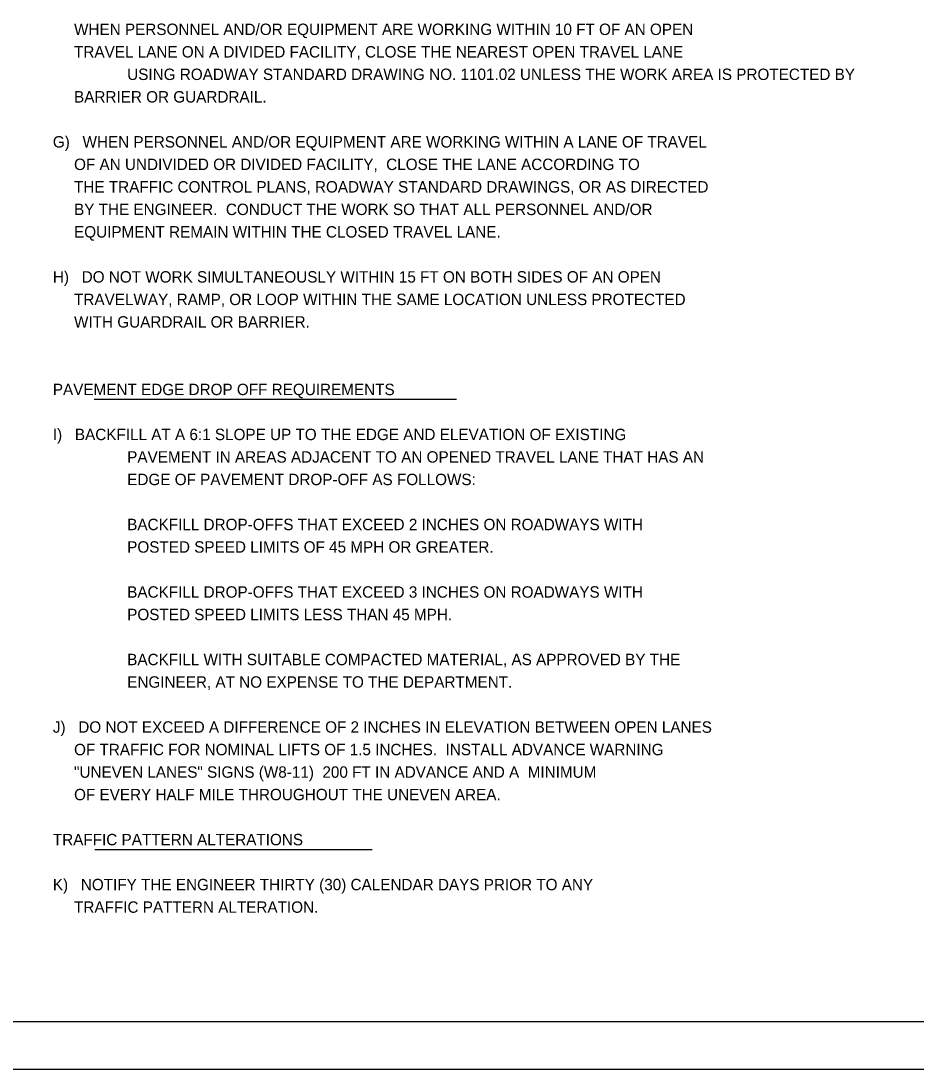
# Model space of a CAD drawing. Extents: x 762655 to 770567, y 650864 to 655190.
# Drawn here: x 763282 to 763752, y 652779 to 653330 of the extents above; entities that cross this region are included whole.
import ezdxf

# ---------------------------------------------------------------- set-up
doc = ezdxf.new("R2010")
doc.units = 0
for name, color, linetype in [('Default', 7, 'Continuous'), ('DEV TRANSPORTATION OPERATIONS PLAN SHEET', 7, 'Continuous'), ('Sheet Plot Border Outside CELL', 7, 'Continuous')]:
    doc.layers.add(name, color=color, linetype=linetype)

msp = doc.modelspace()

# ---------------------------------------------------------------- linework, layer by layer
at = {"layer": 'Default'}
for p, q in [((763320.1, 653130.89), (763510.57, 653130.89)), ((763320.41, 652894.11), (763466.13, 652894.11))]:
    msp.add_line(p, q, dxfattribs=at)
at = {"layer": 'DEV TRANSPORTATION OPERATIONS PLAN SHEET'}
msp.add_lwpolyline([(764317.85, 653853.76), (762817.85, 653853.76), (762817.85, 652803.75), (764317.85, 652803.75)], close=True, dxfattribs=at)
at = {"layer": 'Sheet Plot Border Outside CELL'}
msp.add_lwpolyline([(762654.85, 652778.75), (764342.85, 652778.75), (764342.85, 653878.75), (762654.85, 653878.75)], close=True, dxfattribs=at)

# ---------------------------------------------------------------- texts
at = {"layer": 'Default'}
for s, p in [('            WHEN PERSONNEL AND/OR EQUIPMENT ARE WORKING WITHIN 10 FT OF AN OPEN', (763282.77, 653322.4)), ('            TRAVEL LANE ON A DIVIDED FACILITY, CLOSE THE NEAREST OPEN TRAVEL LANE', (763282.77, 653310.57)), ('   USING ROADWAY STANDARD DRAWING NO. 1101.02 UNLESS THE WORK AREA IS PROTECTED BY ', (763330.77, 653298.74)), ('            BARRIER OR GUARDRAIL.', (763282.77, 653286.9)), ('       G)   WHEN PERSONNEL AND/OR EQUIPMENT ARE WORKING WITHIN A LANE OF TRAVEL', (763282.77, 653263.24)), ('            OF AN UNDIVIDED OR DIVIDED FACILITY,  CLOSE THE LANE ACCORDING TO', (763282.77, 653251.4)), ('            THE TRAFFIC CONTROL PLANS, ROADWAY STANDARD DRAWINGS, OR AS DIRECTED', (763282.77, 653239.57)), ('            BY THE ENGINEER.  CONDUCT THE WORK SO THAT ALL PERSONNEL AND/OR ', (763282.77, 653227.74)), ('            EQUIPMENT REMAIN WITHIN THE CLOSED TRAVEL LANE.', (763282.77, 653215.9)), ('       H)   DO NOT WORK SIMULTANEOUSLY WITHIN 15 FT ON BOTH SIDES OF AN OPEN', (763282.77, 653192.24)), ('            TRAVELWAY, RAMP, OR LOOP WITHIN THE SAME LOCATION UNLESS PROTECTED ', (763282.77, 653180.4)), ('            WITH GUARDRAIL OR BARRIER.', (763282.77, 653168.57)), ('       PAVEMENT EDGE DROP OFF REQUIREMENTS', (763282.77, 653133.07)), ('       I)   BACKFILL AT A 6:1 SLOPE UP TO THE EDGE AND ELEVATION OF EXISTING', (763282.77, 653109.4)), ('   PAVEMENT IN AREAS ADJACENT TO AN OPENED TRAVEL LANE THAT HAS AN ', (763330.77, 653097.57)), ('   EDGE OF PAVEMENT DROP-OFF AS FOLLOWS:', (763330.77, 653085.74)), ('   BACKFILL DROP-OFFS THAT EXCEED 2 INCHES ON ROADWAYS WITH ', (763330.77, 653062.07)), ('   POSTED SPEED LIMITS OF 45 MPH OR GREATER.', (763330.77, 653050.24)), ('   BACKFILL DROP-OFFS THAT EXCEED 3 INCHES ON ROADWAYS WITH', (763330.77, 653026.57)), ('   POSTED SPEED LIMITS LESS THAN 45 MPH.', (763330.77, 653014.74)), ('   BACKFILL WITH SUITABLE COMPACTED MATERIAL, AS APPROVED BY THE', (763330.77, 652991.07)), ('   ENGINEER, AT NO EXPENSE TO THE DEPARTMENT.', (763330.77, 652979.24)), ('       J)   DO NOT EXCEED A DIFFERENCE OF 2 INCHES IN ELEVATION BETWEEN OPEN LANES', (763282.77, 652955.57)), ('            OF TRAFFIC FOR NOMINAL LIFTS OF 1.5 INCHES.  INSTALL ADVANCE WARNING', (763282.77, 652943.74)), ('            "UNEVEN LANES" SIGNS (W8-11)  200 FT IN ADVANCE AND A  MINIMUM ', (763282.77, 652931.9)), ('            OF EVERY HALF MILE THROUGHOUT THE UNEVEN AREA.', (763282.77, 652920.07)), ('       TRAFFIC PATTERN ALTERATIONS', (763282.77, 652896.4)), ('       K)   NOTIFY THE ENGINEER THIRTY (30) CALENDAR DAYS PRIOR TO ANY', (763282.77, 652872.74)), ('            TRAFFIC PATTERN ALTERATION.', (763282.77, 652860.9))]:
    msp.add_text(s, height=6, dxfattribs=at).set_placement(p)

doc.saveas('drawing.dxf')
